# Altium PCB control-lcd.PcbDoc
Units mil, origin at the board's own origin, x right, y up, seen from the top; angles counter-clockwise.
Board outline 3313 x 2255 mil, 2 copper layers (Top Layer, Bottom Layer); 62 components, 67 nets, 308 pads, 239 vias.
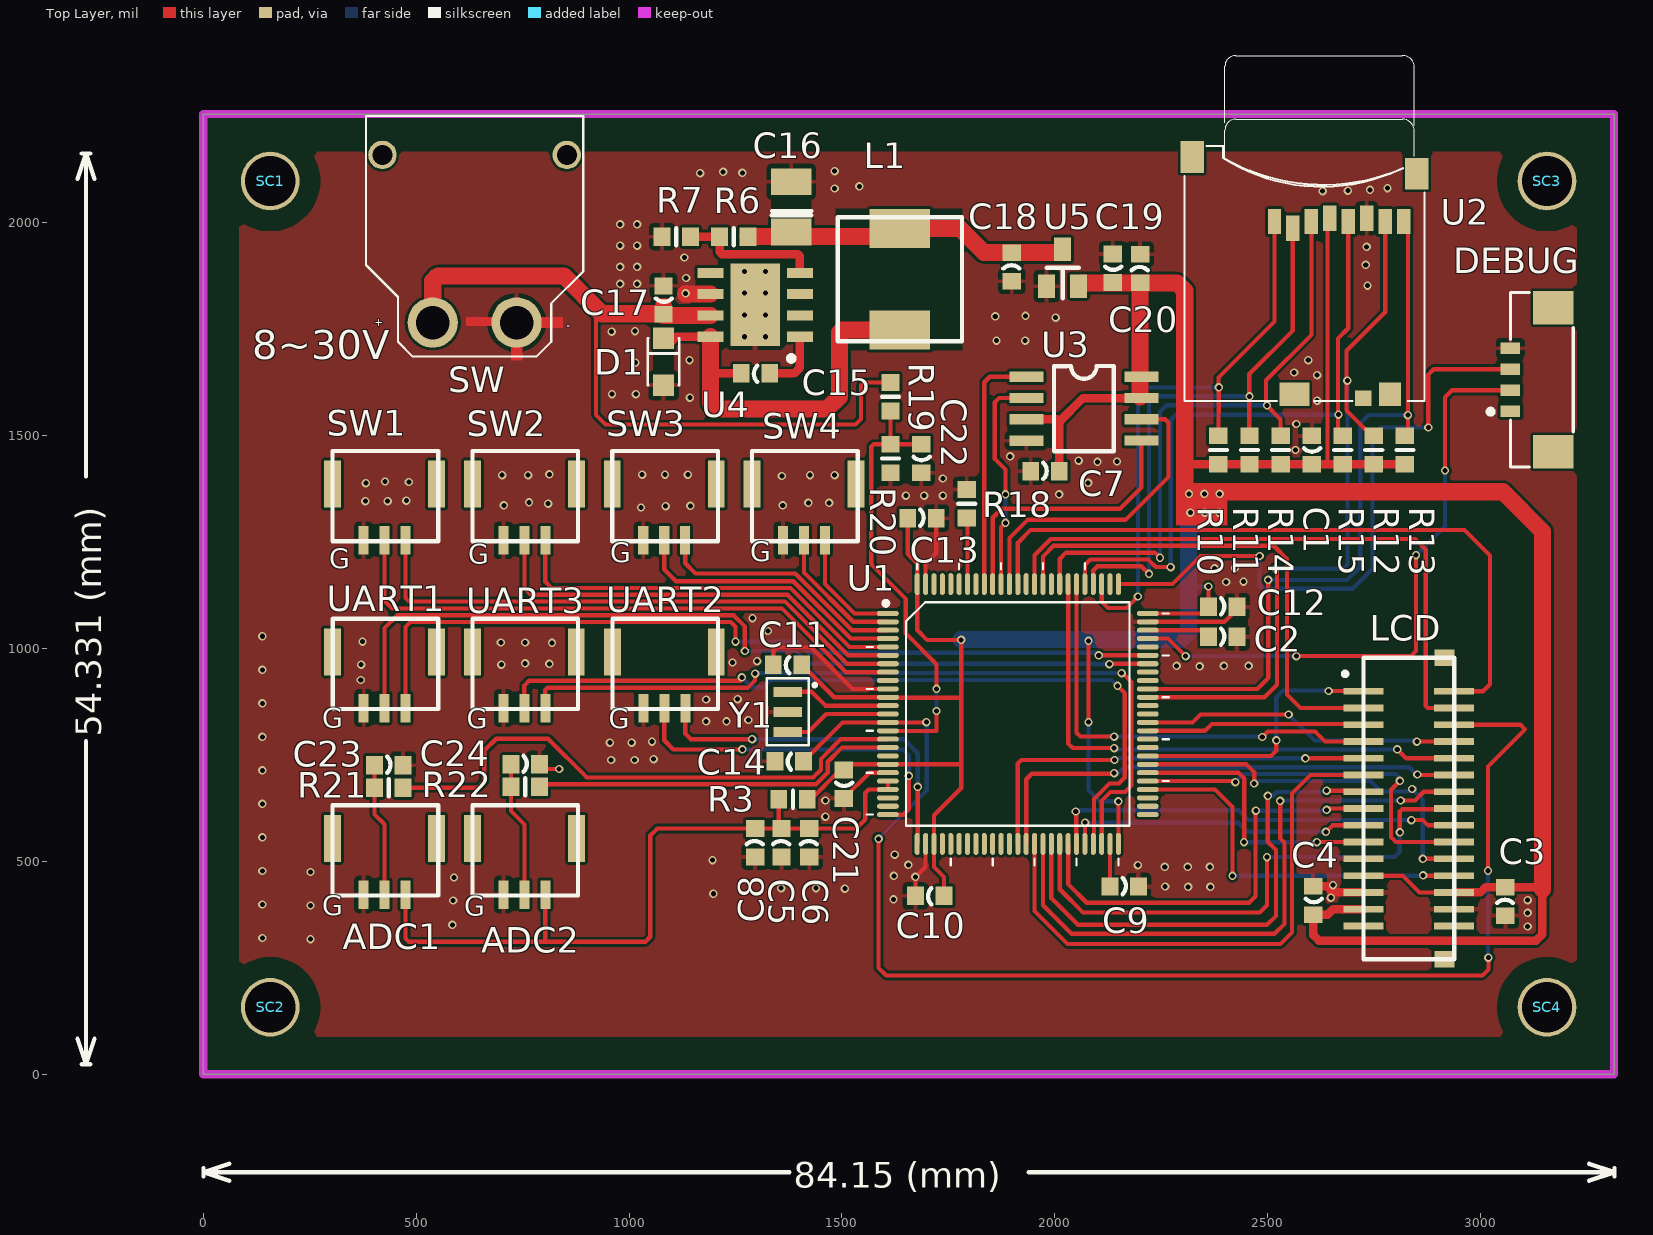
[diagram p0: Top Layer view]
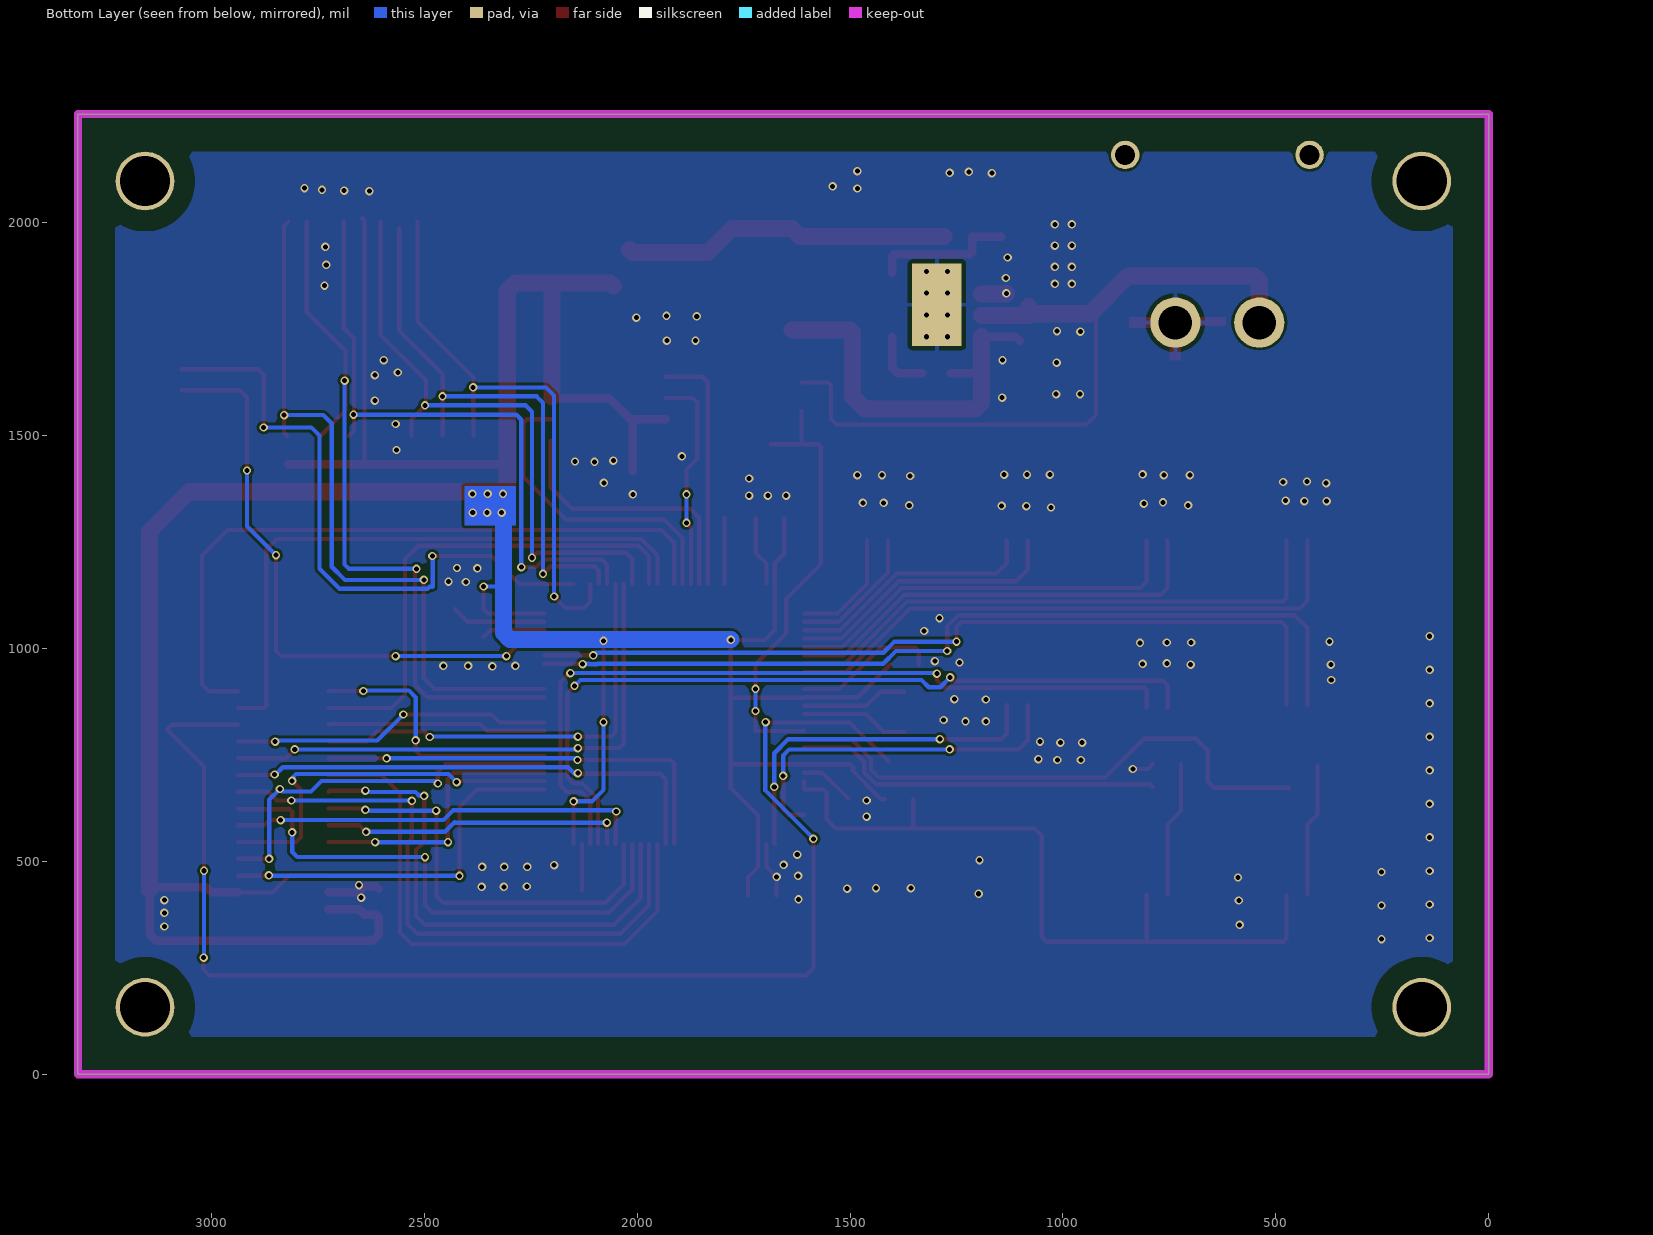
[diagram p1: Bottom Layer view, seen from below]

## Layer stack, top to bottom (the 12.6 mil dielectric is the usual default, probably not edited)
Top Solder: solder mask 0.4, Solder Resist, Dk 3.5
Top Layer: signal copper 1.4
Dielectric 1: dielectric 12.6, FR-4, Dk 4.8
Bottom Layer: signal copper 1.4
Bottom Solder: solder mask 0.4, Solder Resist, Dk 3.5

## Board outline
0,0 3313,0 3313,2255 0,2255

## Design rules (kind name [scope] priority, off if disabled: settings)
Clearance [All] p1: gap=6 ignorepadtopadclearanceinfootprint=FALSE
ComponentClearance [All] p1: gap=0 collisioncheckmode=3 verticalgap=0 showdistances=FALSE
HoleToHoleClearance [All] p1: gap=0 allowstackedmicrovias=TRUE
MinimumSolderMaskSliver [All] p1: minsoldermaskwidth=0
PolygonConnect PolygonConnect_1 [All vs IsVia] p1: connectstyle=Direct reliefconductorwidth=10 reliefentries=4 polygonreliefangle="90 Angle" airgapwidth=10
PolygonConnect [All] p2: connectstyle=Relief reliefconductorwidth=10 reliefentries=4 polygonreliefangle="90 Angle" airgapwidth=10
RoutingVias [All] p1: holewidth=28 width=50 viastyle="Through Hole" minholewidth=11.81 minwidth=19.68 maxholewidth=28 maxwidth=50
SilkToSilkClearance [All] p1: silktosilkclearance=0
SilkToSolderMaskClearance [IsPad] p1: minsilkscreentomaskgap=0 clearancetoexposedcopper=TRUE
SolderMaskExpansion [All] p1: expansion=4
Width [All] p1: maxlimit=60 minlimit=6 preferedwidth=15
25 further rules are at their usual default settings.

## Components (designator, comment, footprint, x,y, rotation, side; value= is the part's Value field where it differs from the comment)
ADC1 "Header 3" 3PJST1.25 548,554 r180 top
ADC2 "Header 3" 3PJST1.25 876.35,554 r180 top
C1 "100n" C0603 2603,1466 r90 top
C2 "225" C0603 2394,1027 r180 top
C3 "100n" C0603 3058,406 r270 top
C4 "100n" C0603 2607,408 r90 top
C5 "100n" C0603 1358,544 r270 top
C6 "10uf" C0603 1423,544 r270 top
C7 "100n" C0603 1977,1416 r180 top
C8 "225" C0603 1296,544 r270 top
C9 "225" C0603 2163,441 r180 top
C10 "100n" C0603 1706,419 r0 top
C11 "100n" C0603 1372,962 r0 top
C12 "100n" C0603 2394,1098 r180 top
C13 "100n" C0603 1688,1306 r180 top
C14 "100n" C0603 1376.54,735 r0 top
C15 "100n" C0603 1297,1646 r0 top
C16 "220u/20V" SMC_B 1381,2037 r90 top
C17 "10uf" C0603 1081,1818 r90 top
C18 "100n" C0603 1899,1896 r270 top
C19 "100n" C0603 2136,1893 r90 top
C20 "10UF" C0603 2200,1892 r270 top
C21 "100n" C0603 1504,681 r90 top
C22 "0.1uF" C0603 1686,1446 r90 top
C23 "0.1uF" C0603 436,726 r180 top
C24 "0.1uF" C0603 756,728 r180 top
D1 "PMEG3010ER" "SOD123W-DIODE - AK" 1081,1673 r90 top
DEBUG "CON4" DF13-1.25-4A 3120,1631 r90 top
L1 "18uH" L7_7_4 1636,1867 r90 top
LCD "Header 15X2A" DIP1.0X30 2725,899.59 r270 top locked
R3 "10R" R0603 1385,646 r0 top
R6 "10k" R0603 1246,1967 r0 top
R7 "3.24k" R0603 1111,1967 r180 top
R10 "4.7K" R0603 2384,1466 r270 top
R11 "4.7K" R0603 2457,1466 r270 top
R12 "4.7K" R0603 2749,1466 r270 top
R13 "4.7K" R0603 2822,1466 r270 top
R14 "4.7K" R0603 2530,1466 r270 top
R15 "4.7K" R0603 2676,1466 r270 top
R18 "4.7K" R0603 1793,1340 r90 top
R19 "10K" R0603 1614,1591 r270 top
R20 "10K" R0603 1614,1446 r270 top value=1K
R21 "10K" R0603 436,673 r180 top value=100R
R22 "10K" R0603 756,675 r180 top value=100R
SC1 "M3" SCRREW_M3#1 132,2083 r0 top
SC2 "M3" SCRREW_M3#2 125,109 r0 top
SC3 "M3" SCRREW_M3#3 3190,2081 r0 top
SC4 "M3" SCRREW_M3#4 3169,157.48 r0 top
SW "TX30" TX30-m 637.46,1765.3 r0 top locked
SW1 "Header 3" 3PJST1.25 548,1385.89 r180 top
SW2 "Header 3" 3PJST1.25 876.35,1385.89 r180 top
SW3 "Header 3" 3PJST1.25 1204.7,1385.89 r180 top
SW4 "Header 3" 3PJST1.25 1533.05,1385.89 r180 top
U1 "STM32F407_100P" ST_LQFP100 1913,846 r0 top locked
U2 "microSD" MICROSD1 2586.21,1870.79 r0 top
U3 "W25Q128" SOIC-8 1933,1638.06 r0 top
U4 "TPS5430DDA" SOIC 1296,1807 r180 top
U5 "3.3V" SOT23 2018,1894 r0 top
UART1 "Header 3" 3PJST1.25 548.05,991.89 r180 top
UART2 "Header 3" 3PJST1.25 1205.05,991.89 r180 top
UART3 "Header 3" 3PJST1.25 876.26,991.89 r180 top
Y1 "CSTCE8M00G55R0" CRYSMD3.2X1.3 1373,851 r270 top

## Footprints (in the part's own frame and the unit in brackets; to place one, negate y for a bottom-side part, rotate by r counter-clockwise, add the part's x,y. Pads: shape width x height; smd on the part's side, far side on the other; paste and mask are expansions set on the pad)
3PJST1.25 [mm]
  rect 1x2.8 smd: 0(0,0) 0(6.2,0)
  rect 0.6x1.7 smd: 1(1.85,3.35) 2(3.1,3.35) 3(4.35,3.35)
  silkscreen extent -0.1,-1.98 6.2,3.4
C0603 [mm] "C0603"
  rect 1x1.1 smd: 1(-0.85,0) 2(0.85,0)
  Top Layer pour cut-out: -0.356,0.533 -0.356,-0.533 0.356,-0.533 0.356,0.533
  silkscreen extent -0.1,-0.51 0.1,0.46
CRYSMD3.2X1.3 [mm]
  rect 0.6x1.7 smd: 1(-1.2,0) 2(0,0) 3(1.2,0)
  Top Layer pour cut-out: -2.007,1.245 -0.381,1.245 -0.381,-1.27 -2.007,-1.27
  Top Layer pour cut-out: 1.981,1.245 0.406,1.245 0.406,-1.245 1.956,-1.245 1.981,-1.219
  silkscreen extent -2,-1.25 2,1.7
DF13-1.25-4A [mm] "佳能"
  rect 0.7x1.18 smd: 1(-1.875,1.28) 2(-0.625,1.28) 3(0.625,1.28) 4(1.875,1.28)
  rect 2x2.4 smd: NC(-4.3,-1.28) NC(4.3,-1.28)
  silkscreen extent -5.21,-2.48 5.21,2.61
DIP1.0X30 [mm]
  rect 0.4x2.4 smd: 1(0,5.39) 2(1,5.39) 3(2,5.39) 4(3,5.39) 5(4,5.39) 6(5,5.39) 7(6,5.39) 8(7,5.39) 9(8,5.39) 10(9,5.39) 11(10,5.39) 12(11,5.39) 13(12,5.39) 14(13,5.39) 15(14,5.39) 16(0,0) 17(1,0) 18(2,0) 19(3,0) 20(4,0) 21(5,0) 22(6,0) 23(7,0) 24(8,0) 25(9,0) 26(10,0) 27(11,0) 28(12,0) 29(13,0) 30(14,0)
  rect 1x1.2 smd: ""(-2,4.816) ""(15.985,4.816)
  Top Layer pour cut-out: -1.88,5.309 -1.88,0.14 -1.968,0.051 10.884,0.051 10.884,5.283 10.858,5.309
  silkscreen extent -2,-1.23 15.98,5.4
L7_7_4 [mm]
  rect 2.35x3.6 smd: 1(3.025,0) 2(-3.025,0)
  Top Layer pour cut-out: -4.242,3.835 -4.242,-3.708 4.216,-3.708 4.216,3.835
  silkscreen extent -3.7,-3.7 3.7,3.7
MICROSD1 [mm]
  rect 0.8x1.5 smd: 1(-1.79,3.346) 2(-0.69,2.946) 3(0.41,3.346) 4(1.51,3.545) 5(2.61,3.346) 6(3.71,3.545) 7(4.81,3.346) 8(5.91,3.346)
  rect 1.4x1.9 smd: NC(-6.7,7.195) NC3(6.7,6.195)
  rect 1.8x1.4 smd: NC1(-0.6,-6.954)
  rect 1x0.9 smd: NC2(3.497,-7.195)
  rect 1.3x1.4 smd: NC2(5.1,-6.954)
  silkscreen extent -7.15,-7.35 7.15,13.25
R0603 [mm] "R0603"
  rect 1x1.1 smd: 1(-0.85,0) 2(0.85,0)
  Top Layer pour cut-out: -0.356,0.533 -0.356,-0.533 0.356,-0.533 0.356,0.533
  silkscreen extent 0,-0.51 0,0.51
SCRREW_M3#1 [mm]
  round 3.5 hole 3: 0(0.647,0.369)
SCRREW_M3#2 [mm]
  round 3.5 hole 3: 0(0.825,1.231)
SCRREW_M3#3 [mm]
  round 3.5 hole 3: 0(-0.876,0.42)
SCRREW_M3#4 [mm]
  round 3.5 hole 3: 0(-0.343,0)
SMC_B [mil] "SMC_B"
  rect 62.99x94.49 smd: +(-59.06,0) -(59.06,0)
  Top Layer pour cut-out: -28,47 -28,-47 28,-47 28,47
  silkscreen extent -20,-48 -10,46
"SOD123W-DIODE - AK" [mil] "SOD123W-DIODE"
  rect 50x50 smd: A(-55.12,0) K(55.12,0)
  Top Layer pour cut-out: -30,25 -30,-25 30,-25 30,25
  silkscreen extent -55,-37 55,37
SOIC [mm]
  rect 1.55x0.6 smd: 1(-2.667,1.905) 2(-2.667,0.635) 3(-2.667,-0.635) 4(-2.667,-1.905) 5(2.667,-1.905) 6(2.667,-0.635) 7(2.667,0.635) 8(2.667,1.905)
  rect 2.95x4.9 smd: 9(0,0)
  rect 2.95x4.9 smd far side: 9(0,0)
  silkscreen extent -2.29,3.07 -2.03,3.33
SOIC-8 [mil]
  rect 80x24 smd: 1(0,0) 2(0,-50.06) 3(0,-100.06) 4(0,-150.06) 5(270,-150) 6(270,-100) 7(270,-50) 8(270,0)
  silkscreen extent 65,-175 205,25
SOT23 [mm] "SOT23"
  rect 1x1.4 smd: 1(-0.95,-1.1) 2(0.95,-1.1) 3(0,1.1)
  silkscreen extent -0.94,-1.82 0.97,0
ST_LQFP100 [mm]
  oval 1.3x0.3 smd: 1(-7.75,6) 2(-7.75,5.5) 3(-7.75,5) 4(-7.75,4.5) 5(-7.75,4) 6(-7.75,3.5) 7(-7.75,3) 8(-7.75,2.5) 9(-7.75,2) 10(-7.75,1.5) 11(-7.75,1) 12(-7.75,0.5) 13(-7.75,0) 14(-7.75,-0.5) 15(-7.75,-1) 16(-7.75,-1.5) 17(-7.75,-2) 18(-7.75,-2.5) 19(-7.75,-3) 20(-7.75,-3.5) 21(-7.75,-4) 22(-7.75,-4.5) 23(-7.75,-5) 24(-7.75,-5.5) 25(-7.75,-6) 51(7.75,-6) 52(7.75,-5.5) 53(7.75,-5) 54(7.75,-4.5) 55(7.75,-4) 56(7.75,-3.5) 57(7.75,-3) 58(7.75,-2.5) 59(7.75,-2) 60(7.75,-1.5) 61(7.75,-1) 62(7.75,-0.5) 63(7.75,0) 64(7.75,0.5) 65(7.75,1) 66(7.75,1.5) 67(7.75,2) 68(7.75,2.5) 69(7.75,3) 70(7.75,3.5) 71(7.75,4) 72(7.75,4.5) 73(7.75,5) 74(7.75,5.5) 75(7.75,6)
  oval 0.3x1.3 smd: 26(-6,-7.75) 27(-5.5,-7.75) 28(-5,-7.75) 29(-4.5,-7.75) 30(-4,-7.75) 31(-3.5,-7.75) 32(-3,-7.75) 33(-2.5,-7.75) 34(-2,-7.75) 35(-1.5,-7.75) 36(-1,-7.75) 37(-0.5,-7.75) 38(0,-7.75) 39(0.5,-7.75) 40(1,-7.75) 41(1.5,-7.75) 42(2,-7.75) 43(2.5,-7.75) 44(3,-7.75) 45(3.5,-7.75) 46(4,-7.75) 47(4.5,-7.75) 48(5,-7.75) 49(5.5,-7.75) 50(6,-7.75) 76(6,7.75) 77(5.5,7.75) 78(5,7.75) 79(4.5,7.75) 80(4,7.75) 81(3.5,7.75) 82(3,7.75) 83(2.5,7.75) 84(2,7.75) 85(1.5,7.75) 86(1,7.75) 87(0.5,7.75) 88(0,7.75) 89(-0.5,7.75) 90(-1,7.75) 91(-1.5,7.75) 92(-2,7.75) 93(-2.5,7.75) 94(-3,7.75) 95(-3.5,7.75) 96(-4,7.75) 97(-4.5,7.75) 98(-5,7.75) 99(-5.5,7.75) 100(-6,7.75)
  silkscreen extent -9.02,-9.02 9.02,9.02
TX30-m [mm]
  round 1.7 hole 1.2: 0(-5.5,10) 0(5.5,10)
  round 3 hole 2: 1(-2.5,0) 2(2.5,0)
  silkscreen extent -6.48,-2.03 6.48,12.32

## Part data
ADC1 ADC2 SW1 SW2 SW3 SW4 UART1 UART2 UART3: "Header, 3-Pin"
C1 C3 C4 C5 C6 C7 C10 C11 C12 C13 C14 C15 C17 C18 C19 C21: library part C-EUC0603, "CAPACITOR, European symbol"
C2 C8 C9: library part C
C16: library part CPOL-EUSMCB, "POLARIZED CAPACITOR, European symbol"
C20 C22 C23 C24: library part Cap, "Capacitor"
D1: library part DIODE-SCHOTTKYSOD123-W
L1: library part L-EU_L0603
LCD: "Header, 15-Pin, Dual row"
R3: library part R
R6 R7 R10 R11 R12 R13 R14 R15 R18: library part R-EU_R0603, "RESISTOR, European symbol"
R19 R20 R21 R22: library part Res2, "Resistor"
SC1 SC2 SC3 SC4: library part Screw_M3, "Screw"
SW: library part "Header 2", "Header, 2-Pin"
U3: library part W25X16, "W25X16;SST25VF016;MX25L1605"
U5: library part XC6206
Y1: library part XTAL-3

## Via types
v1: diameter 19.68, hole 11.81, Top Layer to Bottom Layer, tented both sides, 239 vias

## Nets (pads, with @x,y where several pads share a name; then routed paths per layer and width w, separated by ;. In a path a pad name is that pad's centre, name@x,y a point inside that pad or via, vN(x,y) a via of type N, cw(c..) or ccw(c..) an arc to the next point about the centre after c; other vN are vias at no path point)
ADC1: R21.1 U1.16 | length 1318
  Top Layer w10: R21.1 645,673 660,688 660,760 688,788 810,788 901,697 1432.37,697 1450.64,715.27 1450.64,740.63 1496.96,786.95 U1.16
ADC2: R22.1 U1.17 | length 871.5
  Top Layer w10: R22.1 795.46,681 1439,681 1466.64,708.64 1466.64,734 1499.9,767.26 U1.17
ADC_C: C22.2 R19.2 R20.1 U1.15 | length 1039.9
  Top Layer w10: U1.15 1608.35,806.16 1721.84,806.16 1722,806.31 v1(1722,853) ; R20.1 1574.46,1479.46 1569,1474 1569,1197 1650,1116 1650,1035 1722,963 v1(1722,905) ; R19.2 1614,1484.46 1619,1479.46 C22.2
  Bottom Layer w10: v1(1722,853) v1(1722,905)
F_CS: U1.92 U3.1 | length 578.2
  Top Layer w10: U1.92 1834.26,1625.26 1847.06,1638.06 U3.1
FSMC_A16: LCD.16 U1.58 | length 644.2
  Top Layer w10: U1.58 2507.58,747.58 2520,760 v1(2520,784) ; v1(2643,900) 2724.59,900 LCD.16
  Bottom Layer w10: v1(2520,784) 2520,885 2536,901 2642,901 v1(2643,900)
FSMC_D0: LCD.18 U1.61 | length 514.4
  Top Layer w10: U1.61 2352.63,806.63 2368.84,822.84 2723.01,822.84 LCD.18
FSMC_D1: LCD.4 U1.62 | length 752.3
  Top Layer w10: U1.62 2323.32,826.32 2342,845 v1(2549,845) ; v1(2850,781) 2850.48,781.48 LCD.4
  Bottom Layer w10: v1(2549,845) 2610.16,783.84 v1@2850,783.84
FSMC_D2: LCD.19 U1.81 | length 1041.9
  Top Layer w10: U1.81 2050.8,802.2 2060,793 v1(2139,793) ; v1(2487,792) 2499.84,804.84 2611.16,804.84 2634.52,781.48 LCD.19
  Bottom Layer w10: v1(2139,793) v1@2487,793
FSMC_D3: LCD.5 U1.82 | length 1294.7
  Top Layer w10: U1.82 2031.11,776.89 2042,766 v1(2139,766) ; v1(2804,763) 2824.89,742.11 LCD.5
  Bottom Layer w10: v1(2139,766) 2142,763 v1(2804,763)
FSMC_D4: LCD.20 U1.38 | length 1009.1
  Top Layer w10: U1.38 1913,730 1921,738 v1(2140,738) v1@2143,738 ; v1(2588,742) 2702.89,742 2703,742.11 LCD.20
  Bottom Layer w10: v1(2140,738) 2144,742 v1(2588,742)
FSMC_D5: LCD.6 U1.39 | length 1184.7
  Top Layer w10: U1.39 1932.69,692.69 1945.84,705.84 2143.16,705.84 2142,707 v1(2139,707) ; v1(2851,704) 2852.26,702.74 LCD.6
  Bottom Layer w10: v1(2139,707) 2148,707 2162,721 2832,721 2850,703 v1(2851,704)
FSMC_D6: LCD.21 U1.40 | length 1317.8
  Top Layer w10: U1.40 1952.37,383.63 2030,306 2530,306 2556.74,332.74 2556.74,659.48 2600,702.74 LCD.21
FSMC_D7: LCD.7 U1.41 | length 1458.3
  Top Layer w10: U1.41 1972.06,396.94 2039,330 2516,330 2539,353 2539,544 2529,554 v1(2529,642) ; v1(2812,643) 2846,643 2866.37,663.37 LCD.7
  Bottom Layer w10: v1(2529,642) 2530,643 v1(2812,643)
FSMC_D8: LCD.22 U1.42 | length 1239.8
  Top Layer w10: U1.42 1991.74,413.26 2054,351 2498,351 2519,372 2519,527 ; v1(2500,654) 2500,546 ; v1(2638,666) 2722.37,666 LCD.22 ; 2500,546 2519,527 ; 2500,546 2519,527
  Bottom Layer w10: v1(2500,654) 2511.52,654 2520.37,662.84 2635.84,662.84 2637,664 2638,663 v1(2638,666)
FSMC_D9: LCD.8 U1.43 | length 1277.6
  Top Layer w10: U1.43 2011.43,434.57 2066,380 2481,380 2498,397 v1(2498,510) ; v1(2810,568) 2810,617 2815.16,622.16 2935.35,622.16 LCD.8
  Bottom Layer w10: v1(2498,510) 2798,510 2810,522 v1(2810,568)
FSMC_D10: LCD.23 U1.44 | length 1017.3
  Top Layer w10: U1.44 2031.11,446.89 2075,403 2456,403 2471,418 v1@2471,622 ; v1(2638,621) 2641,624 LCD.23
  Bottom Layer w10: v1(2472,619) 2636,619 v1(2638,621)
FSMC_D11: LCD.9 U1.45 | length 987.1
  Top Layer w10: v1(2049,617) v1@2051,617 ; v1@2050.16,617 2050.16,541.52 U1.45 ; v1(2837,597) 2863.63,597 2876,584.63 LCD.9
  Bottom Layer w10: v1(2049,617) 2049,617.69 2046.84,619.84 2432.16,619.84 2455,597 v1(2837,597)
FSMC_D12: LCD.24 U1.46 | length 716.6
  Top Layer w10: U1.46 v1@2070.48,587.48 ; v1(2636.52,569.48) 2651.67,584.63 LCD.24
  Bottom Layer w10: v1(2071,591) 2428,591 2429,592 2451.52,569.48 v1(2636.52,569.48)
FSMC_D13: LCD.10 U1.55 | length 905.2
  Top Layer w10: U1.55 2421.48,688.52 v1(2424,686) ; v1(2810,689) 2789.16,668.16 2789.16,556.84 2800.74,545.26 LCD.10
  Bottom Layer w10: v1(2424,686) 2443,705 2801,705 2810,696 v1(2810,689)
FSMC_D14: LCD.25 U1.56 | length 663.1
  Top Layer w10: U1.56 2431.27,708.21 2444.84,694.63 2444.84,545.84 v1(2444,545) ; v1@2615.26,545.26 LCD.25
  Bottom Layer w10: v1(2444,545) v1(2615,545)
FSMC_D15: LCD.11 U1.57 | length 916.2
  Top Layer w10: U1.57@2220.12,727.89 2450,727.89 2468,709.89 v1(2468,683) ; v1(2864,506) 2937.09,506 LCD.11
  Bottom Layer w10: v1(2468,683) 2474,689 2741,689 2766,664 2766.16,664.16 2833.16,664.16 v1(2839,670) 2864,645 v1(2864,506)
FSMC_NE1: LCD.1 U1.88 | length 1636.8
  Top Layer w10: U1.88 1913,1248 1943,1278 2962,1278 3022,1218 3022,916 3005.59,899.59 LCD.1
FSMC_NOE: LCD.17 U1.85 | length 1172.2
  Top Layer w10: U1.85 1972.06,1216.06 1997,1241 2514,1241 2545,1210 2545,892 2576.78,860.22 LCD.17
FSMC_NWE: LCD.2 U1.86 | length 1447.8
  Top Layer w10: U1.86 1952.37,1219 1990.37,1257 2846,1257 2871,1232 2871,865 2875.78,860.22 LCD.2
GND: ADC1.3 ADC2.3 C1.2 C2.1 C3.2 C4.2 C5.2 C6.2 C7.2 C8.2 C9.1 C10.1 C11.1 C12.1 C13.1 C14.1 C16.- C17.2 C18.2 C19.2 C20.1 C21.1 C22.1 C23.1 C24.1 D1.A DEBUG.4 LCD.14 LCD.26 LCD.28 R7.2 R18.2 R20.2 SW1.3 SW2.3 SW3.3 SW4.3 SW.2 U1.10 U1.20 U1.27 U1.74 U1.99 U2.6 U3.4 U4.6 U4.9 U5.1 UART1.3 UART2.3 UART3.3 Y1.2 | length 1230.5
  Top Layer w10: C24.1 800.46,717 v1(836,717) ; C11.1 1338.54,993.54 1347,1002 1428,1002 1524.94,905.06 U1.10 ; C21.1 1564.67,708.21 U1.20 ; C10.1 v1(1672.54,463.54) 1696.47,487.47 U1.27 ; U1.99 1696.47,1199.47 1721.46,1224.46 C13.1 ; U1.74 2398,1062.54 C12.1@2427.46,1092
  Top Layer w20: C4.2@2607,435.46 2613,441.46 2639.54,441.46 2653.85,427.15 LCD.28
  Top Layer w40: v1(1133,1834) 1134,1833 1133,1832 U4.6
  other v1: 252,317.52 139,320 3110,347 585,351 3110,379 252,396.26 139,398.74 587,408 3110,409 1621,411 2648,415 1198,424 1507,436 1357,437 1439,437 2313,440 2365,440 2259,441 2653,444 589,462 1622,466 252,475 139,477.48 2258,487 2312,487 2364,487 2195,491 1656,492 1196,503 1624,516 139,556.22 1461,605 139,634.96 1461,643 139,713.7 958,738 1013,738 1058,740 955,779 1006,779 1054,781 139,792.44 1181,829 1229,829 1280,832 139,871.18 1181,880 1255,881 370,926 139,949.92 2340,958 2286,959 2397,959 2455,959 371,962 700,962 813,964 756,965 1243,967 1301,970 819,1013 699,1014 756,1014 374,1016 139,1028.66 1326,1041 1290,1071 2402,1156 2443,1157 2375,1188 2423,1189 1028,1331 1086,1334 1144,1335 706,1336 1361,1336 810,1340 1421,1342 1470,1342 765,1343 381,1346 433,1346 477,1347 1650,1359 1693,1359 1737,1359 2010,1362 382,1388 2078,1389 483,1391 427,1392 1737,1399 1359,1405 702,1407 763,1407 1425,1407 1483,1407 1031,1408 1084.5,1408 1138,1408 813,1409 2100,1438 2146,1439 2056,1441 1895,1451 2565,1466 2567,1527 2616,1582 1143,1589 960,1597 1016,1597 2616,1642 2562,1648 1015,1671 1142,1677 2595,1677 1863,1723 1930,1723 1271,1732 1321,1732 959,1744 1014,1745 2002,1777 1860,1780 1931,1781 1271,1783.18 1321,1783.18 1271,1834.36 1321,1834.36 2734,1852 979,1856 1019,1856 1134,1870 1271,1885.54 1321,1885.54 979,1896 1019,1896 2730,1901 1130,1918 2732,1943 979,1946 1019,1946 979,1996 1019,1996 2629,2074 2688,2075 2740,2077 1483,2080 2781,2081 1541,2085 1167,2116 1266,2117 1221,2119 1483,2121
LCD_BL: LCD.12 U1.54 | length 905.6
  Top Layer w10: U1.54 2376.16,668.84 2417,628 v1(2417,466) ; v1(2865,467) 2862,467 2861.52,466.52 LCD.12
  Bottom Layer w10: v1(2417,466) 2864,466 v1(2865,467)
NetADC1_2: ADC1.2 C23.2 R21.2 | length 313.6
  Top Layer w10: C23.2 R21.2 402.54,610.46 425.95,587.05 ADC1.2
NetADC2_2: ADC2.2 C24.2 R22.2 | length 319
  Top Layer w10: C24.2 R22.2 722.54,618.46 754.3,586.7 ADC2.2
NetC2_2: C2.2 U1.73 | length 149
  Top Layer w10: U1.73 2344.69,1042.85 C2.2
NetC9_2: C9.2 U1.49 | length 109.6
  Top Layer w10: U1.49 2129.54,431.92 C9.2@2130,431.46
NetC15_1: C15.1 D1.K L1.2 U4.8 | length 928.8
  Top Layer w20: D1.K@1101.12,1722 1111.12,1732 U4.8 ; 1201,1646 C15.1
  Top Layer w40: U4.8 1191,1576 1205,1562 1465,1562 1494,1591 1494,1742 1499.91,1747.91 L1.2
NetC15_2: C15.2 U4.1 | length 148.9
  Top Layer w20: C15.2 1388,1646 1401,1659 U4.1
NetR6_1: R6.1 R7.1 U4.4 | length 335.4
  Top Layer w20: R7.1 R6.1 1212.54,1931.46 1218,1926 1396,1926 1401,1921 U4.4
NetR18_1: R18.1 U1.94 | length 155.4
  Top Layer w10: U1.94 R18.1@1794.89,1306.54
NetU1_12: U1.12 Y1.1 | length 248.4
  Top Layer w10: Y1.1 1428.76,898.24 1461.31,865.69 U1.12
NetU1_13: U1.13 Y1.3 | length 252.4
  Top Layer w10: Y1.3 1420.76,803.76 1463,846 U1.13
REST1: C14.2 LCD.3 U1.14 | length 3167.4
  Top Layer w10: C14.2 1501.32,826.32 U1.14 1697.68,826.32 1698,826.63 v1(1698,827) ; v1(1586,553) 1586,250 1604,232 3004,232 3018,246 v1(3018,274) ; LCD.3 3093.15,820.85 3104,810 3017,723 v1(3017,478)
  Bottom Layer w10: v1(1586,553) 1586,553.52 1698.84,666.37 1698.84,826.16 v1(1698,827) ; v1(3017,478) 3017,275 v1(3018,274)
RX1: U1.70 UART1.1 | length 1984.8
  Top Layer w10: UART1.1@475.17,866.11 475.17,1050.17 487,1062 1239,1062 1250,1051 v1(1250,1016) ; v1(2103,984) 2103.2,983.8 2119.32,983.8 2119.37,983.84 U1.70 U1.70
  Bottom Layer w10: v1(1250,1016) 1396,1016 1422,990 2097,990 v1(2103,984)
RX2: U1.26 UART2.1 | length 847.3
  Top Layer w10: UART2.1@1131.86,867.11 1131.86,800.14 1145,787 v1(1289,787) ; U1.26 1678,542.1 v1(1678,675)
  Bottom Layer w10: v1(1289,787) 1645,787 1678,754 v1(1678,675) v1@1677,676
RX3: U1.48 UART3.1 | length 1883
  Top Layer w10: UART3.1 803.42,902.42 809,908 1279,908 1296,925 v1(1296,941) ; U1.48 2109.85,641.85 2131,663 2165,663 2180,678 2180,921 2159,942 v1(2157,942)
  Bottom Layer w10: v1@1296,940.31 1297.84,942.16 2156.84,942.16 v1(2157,942)
SDIO_CK: R15.1 U1.80 U2.5 | length 1522
  Top Layer w10: U1.80 2070.48,1196.48 2083,1209 2219,1209 2237,1191 v1(2272,1191) ; R15.1 2665,1510.46 2665,1728 2688.97,1751.97 U2.5
  Bottom Layer w10: v1(2272,1191) 2272,1537 2284,1549 v1(2666,1549)
SDIO_CMD: R14.1 U1.83 U2.3 | length 1465.2
  Top Layer w10: U1.83 2011.43,1210.43 2026,1225 2235,1225 v1(2247,1213) ; v1@2496,1572 2496,1630 2602.35,1736.35 U2.3 ; v1@2497.5,1570.5 2530,1538 R14.1
  Bottom Layer w10: v1(2247,1213) 2247,1556 2262,1571 v1(2498,1571)
SDIO_D0: R12.1 U1.65 U2.7 | length 1765.1
  Top Layer w10: U1.65 2492.37,885.37 2521.84,914.84 2521.84,1183.16 v1(2518,1187) ; R12.1 2743.54,1499.46 2686.84,1556.16 2686.84,1557.63 2685,1559.48 2685,1699 2775.58,1789.58 U2.7
  Bottom Layer w10: v1(2518,1187) 2677,1187 2687,1197 v1(2687,1629)
SDIO_D1: R13.1 U1.66 U2.8 | length 1718.9
  Top Layer w10: U1.66 2475.06,905.06 2501,931 v1(2501,1161) ; U2.8 2829,1992.4 v1(2829,1548) 2829,1506.46 R13.1
  Bottom Layer w10: v1(2501,1161) 2686,1161 2717,1192 2717,1528 2737,1548 v1(2829,1548)
SDIO_D2: R10.1 U1.78 U2.1 | length 1430.4
  Top Layer w10: U1.78 2109.85,1110.15 2125,1095 2168,1095 v1(2195,1122) ; R10.1 2384,1554 ; v1(2385,1613) 2385,1555 2384,1554 ; U2.1@2515.53,2002.51 2515.53,1767.53 2384,1636 2384,1554
  Bottom Layer w10: v1(2195,1122) 2195,1594 2214,1613 v1(2385,1613)
SDIO_D3: R11.1 U1.79 U2.2 | length 1348.3
  Top Layer w10: U1.79 2090.17,1183.17 2100,1193 2203,1193 v1(2221,1175) ; R11.1@2456.5,1499.46 2456.5,1644.5 2558.84,1746.84 U2.2@2558.84,1986.76
  Bottom Layer w10: v1(2221,1175) 2221,1577 2236,1592 v1(2457,1592)
SPI1_MISO: U1.90 U3.2 | length 519.7
  Top Layer w10: U1.90 1873.63,1284.63 v1(1884,1295) ; v1(1884,1362) 1884,1420 1859,1445 1859,1578 1869,1588 U3.2
  Bottom Layer w10: v1(1884,1295) v1(1884,1362)
SPI1_MOSI: U1.91 U3.5 | length 644.4
  Top Layer w10: U1.91 1853.95,1306.95 1875,1328 2153,1328 2203,1378 U3.5
SPI1_SCK: U1.89 U3.6 | length 735.7
  Top Layer w10: U1.89 1893.32,1259.32 1936,1302 2166,1302 2267,1403 2267,1530 2258.94,1538.06 U3.6
SW1_1: SW1.2 U1.8 | length 1393.3
  Top Layer w10: SW1.2 425.95,1112.05 444,1094 1359.24,1094 1508.81,944.43 U1.8
SW1_2: SW1.1 U1.7 | length 1332
  Top Layer w10: SW1.1 475.17,1118.83 484,1110 1365.86,1110 1511.75,964.11 U1.7
SW2_1: SW2.2 U1.6 | length 1031.3
  Top Layer w10: SW2.2 754.3,1141.7 770,1126 1372.49,1126 1514.69,983.8 U1.6
SW2_2: SW2.1 U1.5 | length 965.3
  Top Layer w10: SW2.1 803.51,1156.49 818,1142 1379.12,1142 1517.64,1003.48 U1.5
SW3_1: SW3.2 U1.4 | length 661.1
  Top Layer w10: SW3.2 1082.65,1185.35 1110,1158 1385.75,1158 1520.58,1023.17 U1.4
SW3_2: SW3.1 U1.3 | length 595
  Top Layer w10: SW3.1 1132,1253.86 1132,1200 1156,1176 1390.37,1176 1523.52,1042.85 U1.3
SW4_1: SW4.2 U1.2 | length 320.7
  Top Layer w10: SW4.2 1411,1178 1526.46,1062.54 U1.2
SW4_2: SW4.1 U1.1 | length 278.9
  Top Layer w10: SW4.1 1460.21,1151.42 1529.41,1082.22 U1.1
SWCLK: DEBUG.3 U1.76 | length 1492.5
  Top Layer w10: U1.76 2276.12,1151.12 2342,1217 v1(2481,1217) ; v1(2877,1519) 2877,1643 2889.6,1655.6 DEBUG.3
  Bottom Layer w10: v1(2481,1217) 2480.16,1216.16 2480.16,1144.84 2487.68,1144.84 2492.37,1140.16 2699.16,1140.16 2746,1187 2746,1500 2765,1519 v1(2877,1519)
SWDIO: DEBUG.2 U1.72 | length 1436.5
  Top Layer w10: U1.72 2265.83,1023.17 v1(2307,982) ; v1(2567,982) 2836,982 2848,994 v1(2848,1219) ; v1(2916,1418) 2916,1590 2932.4,1606.4 DEBUG.2
  Bottom Layer w10: v1(2307,982) v1(2567,982) ; v1(2848,1219) 2916,1287 v1(2916,1418)
TX1: U1.69 UART1.2 | length 2069
  Top Layer w10: UART1.2@425.95,866.11 425.95,1047.95 456,1078 1245.63,1078 1272,1051.63 v1(1272,994) ; v1(2128,963) 2129.11,964.11 U1.69
  Bottom Layer w10: v1(1272,994) 1392,994 1422,964 2093.52,964 2094.37,963.16 2111.63,963.16 2112.48,964 2127,964 v1(2128,963)
TX2: U1.25 UART2.2 | length 853.1
  Top Layer w10: UART2.2@1082.65,867.11 1082.65,784.35 1104,763 v1(1266,763) ; U1.25 1644.78,609.78 1657.16,622.16 1657.16,700.84 v1(1657,701)
  Bottom Layer w10: v1(1266,763) 1643,763 1657,749 v1(1657,701)
TX3: U1.47 UART3.2 | length 1899.3
  Top Layer w10: UART3.2 754.21,913.21 765,924 1261,924 1265,928 v1(1265,932) ; U1.47@2091.84,540.88 2091.84,646.84 2128.16,683.16 2150,683.16 2164,697.16 2164,895 v1(2147,912)
  Bottom Layer w10: v1(1265,932) 1288,909 1315,909 1332,926 2133,926 v1(2147,912)
VCC3.3: C1.1 C3.1 C4.1 C7.1 C10.2 C11.2 C12.2 C13.2 C19.1 C20.2 C21.2 LCD.13 LCD.27 LCD.29 R3.2 R10.2 R11.2 R12.2 R13.2 R14.2 R15.2 U1.11 U1.19 U1.28 U1.50 U1.75 U1.100 U2.4 U3.3 U3.7 U3.8 U5.2 | length 8963.7
  Top Layer w10: C11.2 1482.09,885.37 U1.11 1609.09,884.16 1778.79,884.16 1780,885.37 ; R3.2 1427,646 C21.2@1495.46,714.46 ; C21.2@1490.73,719.19 1499.43,727.89 U1.19 1778,727.89 ; C13.2 1654.54,1222.46 1676.78,1200.22 U1.100 1676.78,1043.22 1700,1020 v1(1780,1020) 1780,885.37 ; C10.2 1739.46,463.54 1716.15,486.85 U1.28 1716.15,608.15 1780,672 1780,885.37 ; v1(2079,827) v1(2079,1018) ; v1(2149,641) 2149.22,640.78 U1.50 ; U1.75 2350.76,1082.22 C12.2@2360.54,1092 ; C12.2 v1(2360.54,1145.54) ; 2640,1432.54 2640,2004.72 U2.4 ; LCD.27 2816.48,466.52 2855.85,427.15 LCD.13
  Top Layer w20: U3.3 2005,1538 2010.46,1532.54 ; C7.1 2010.46,1532.54 ; U3.7 2065.98,1588.06 2010.46,1532.54 ; 2305,1432.54 R10.2 C1.1 2640,1432.54 R13.2@2819,1432.54 ; LCD.29 2653.78,387.78 2640.54,374.54 2613,374.54 2607,368.54 2607,327 2620,314 3130,314 3145,329 3145,434 3139.54,439.46 C3.1 3011.46,439.46 2999.15,427.15 LCD.13
  Top Layer w40: U5.2 2063.25,1858.54 C20.2 ; U3.7@2200,1591.06 C20.2 ; 3145,434 3145,1275 3052,1368 2306,1368 2305,1369 2305,1432.54 2305,1840 2286.46,1858.54 C20.2
  Bottom Layer w10: v1(2079,827) 2079,668 2106,641 v1(2149,641) ; v1(2079,1018) 2116,1018 2118,1020 ; 2314,1145.54 v1(2360.54,1145.54)
  Bottom Layer w40: v1@1780,1021 2116,1021 ; 2118,1021 2299,1021 2314,1036 2314,1145.54 ; 2314,1150 2314,1338
  other v1: 2318,1319 2352,1319 2386,1319 2315,1363 2351,1363 2387,1363
VCC5: C16.+ C18.1 L1.1 R6.2 U5.3 | length 772.7
  Top Layer w40: R6.2 1616.91,1967 L1.1 1776.91,1986.09 1833.54,1929.46 C18.1 2011.15,1929.46 U5.3@2018,1936.31
VCC12V: C17.1 R19.1 SW.1 U4.7 | length 1834.5
  Top Layer w10: 922.46,1786 922.46,1548.54 945,1526 1532,1526 1545,1539 1545,1618 1551.46,1624.46 R19.1
  Top Layer w40: SW.1 539.04,1863.04 551,1875 847,1875 936,1786 1081,1786 C17.1@1081,1803.54 ; C17.1@1081,1782 U4.7
VDD_3V3: DEBUG.1
VDDA: ADC1.1 ADC2.1 C5.1 C6.1 C8.1 R3.1 U1.21 U1.22 | length 1766.6
  Top Layer w10: ADC1.1 475.17,318.83 483,311 807,311 ; ADC2.1 803.51,314.49 807,311 ; R3.1 1351.54,583.92 C5.1 ; U1.21 U1.22 1562.84,668.84 1555,661 1555,599 1533.46,577.46 C6.1 C5.1 ; 807,311 1038,311 1050,323 1050,561 1066.46,577.46 C8.1 C5.1
pads on no net: ADC1.0 ADC2.0 DEBUG.NC LCD. LCD.15 LCD.30 SC1.0 SC2.0 SC3.0 SC4.0 SW1.0 SW2.0 SW3.0 SW4.0 SW.0 U1.9 U1.18 U1.23 U1.24 U1.29 U1.30 U1.31 U1.32 U1.33 U1.34 U1.35 U1.36 U1.37 U1.51 U1.52 U1.53 U1.59 U1.60 U1.63 U1.64 U1.67 U1.68 U1.71 U1.77 U1.84 U1.87 U1.93 U1.95 U1.96 U1.97 U1.98 U2.NC U2.NC1 U2.NC2 U2.NC3 U4.2 U4.3 U4.5 UART1.0 UART2.0 UART3.0

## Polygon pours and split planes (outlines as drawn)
GND on Top Layer "Top Layer-No Net" (solid, remove dead copper, pour order 0): 85,88 3225,88 3225,2166 85,2166
GND on Bottom Layer "Top Layer-No Net" (solid, remove dead copper, pour order 2): 85,88 3225,88 3225,2166 85,2166

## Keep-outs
Keep-Out Layer:
  the board outline again, w19.68

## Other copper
Top Layer:
  rectangle net GND: 755,1753 845,1778
  rectangle net GND: 617,1757 727,1778
  rectangle net GND: 723,1676 750,1762
  rectangle net VCC3.3: 2285,1289 2405,1382
  pour cut-out: 39.37,2097.52 ccw(c157.48,2097.52) 157.48,1979.41 ccw(c157.48,2097.52) 275.59,2097.52 ccw(c157.48,2097.52) 157.48,2215.63 ccw(c157.48,2097.52)
  pour cut-out: 3037.4,2097.52 ccw(c3155.51,2097.52) 3155.51,1979.41 ccw(c3155.51,2097.52) 3273.62,2097.52 ccw(c3155.51,2097.52) 3155.51,2215.63 ccw(c3155.51,2097.52)
  pour cut-out: 3037.4,157.48 ccw(c3155.51,157.48) 3155.51,39.37 ccw(c3155.51,157.48) 3273.62,157.48 ccw(c3155.51,157.48) 3155.51,275.59 ccw(c3155.51,157.48)
  pour cut-out: 39.37,157.48 ccw(c157.48,157.48) 157.48,39.37 ccw(c157.48,157.48) 275.59,157.48 ccw(c157.48,157.48) 157.48,275.59 ccw(c157.48,157.48)
Bottom Layer:
  rectangle net VCC3.3: 2285,1289 2405,1382
  pour cut-out: 39.37,2097.52 ccw(c157.48,2097.52) 157.48,1979.41 ccw(c157.48,2097.52) 275.59,2097.52 ccw(c157.48,2097.52) 157.48,2215.63 ccw(c157.48,2097.52)
  pour cut-out: 3037.4,2097.52 ccw(c3155.51,2097.52) 3155.51,1979.41 ccw(c3155.51,2097.52) 3273.62,2097.52 ccw(c3155.51,2097.52) 3155.51,2215.63 ccw(c3155.51,2097.52)
  pour cut-out: 3037.4,157.48 ccw(c3155.51,157.48) 3155.51,39.37 ccw(c3155.51,157.48) 3273.62,157.48 ccw(c3155.51,157.48) 3155.51,275.59 ccw(c3155.51,157.48)
  pour cut-out: 39.37,157.48 ccw(c157.48,157.48) 157.48,39.37 ccw(c157.48,157.48) 275.59,157.48 ccw(c157.48,157.48) 157.48,275.59 ccw(c157.48,157.48)

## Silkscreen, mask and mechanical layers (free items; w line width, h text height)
Top Overlay:
  lines w10: -295,83.58 -275,23.58 ; -295,2102.58 -275,2162.58 ; -285,23.58 -265,23.58 ; -285,2162.58 -265,2162.58 ; -275,782.18 -275,23.58 ; -275,1403.99 -275,2162.58 ; -255,83.58 -275,23.58 ; -255,2102.58 -275,2162.58 ; 1,-240 1,-220 ; 61,-250 1,-230 ; 61,-210 1,-230 ; 1376.59,-230 1,-230 ; 1938.41,-230 3314,-230 ; 3254,-250 3314,-230 ; 3254,-210 3314,-230 ; 3314,-240 3314,-220
  text "8~30V" at 115,1656 h118.11
  text "G" at 1285,1189 h78.74
  text "G" at 956,1187 h78.74
  text "G" at 623,1184 h78.74
  text "G" at 296,1173 h78.74
  text "G" at 279,798 h78.74
  text "G" at 619,797 h78.74
  text "G" at 952,797 h78.74
  text "54.331 (mm)" at -239.01,792.18 h60 r90
  text "G" at 279,358 h78.74
  text "G" at 613,357 h78.74
  text "84.15 (mm)" at 1386.59,-265.99 h60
